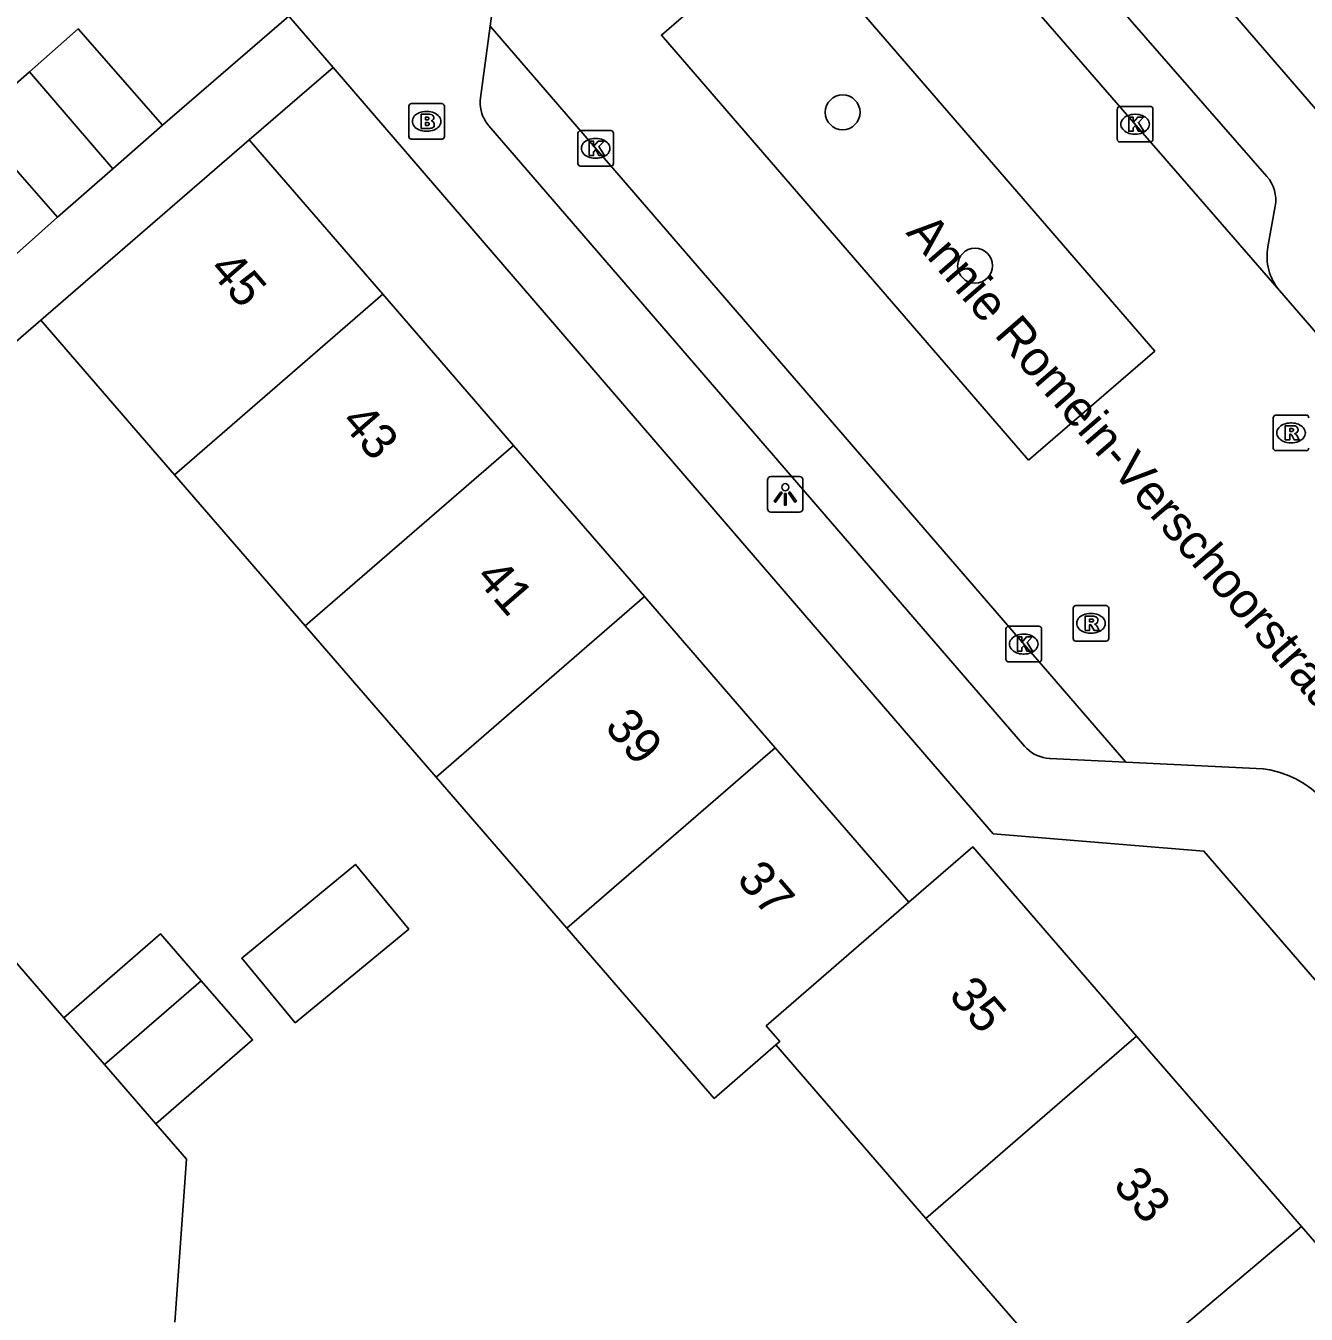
# Model space of a CAD drawing. Extents: x 160304 to 160954, y 383686 to 384161.
# Drawn here: x 160422.39 to 160458.42, y 384042.77 to 384079.01 of the extents above; entities that cross this region are included whole.
import ezdxf

# ---------------------------------------------------------------- set-up
doc = ezdxf.new("R2010")
doc.units = 0
for name, color, linetype in [('IMGEO_Boom', 7, 'Continuous'), ('IMGEO_Brandkraan', 7, 'Continuous'), ('IMGEO_Kolk', 7, 'Continuous'), ('IMGEO_Lichtpunt', 7, 'Continuous'), ('IMGEO_Openbare_ruimte_label', 7, 'Continuous'), ('IMGEO_Pand', 7, 'Continuous'), ('IMGEO_Pand_nummerreeks', 7, 'Continuous'), ('IMGEO_Rijbaan_lokaal_open', 7, 'Continuous'), ('IMGEO_Rioolput', 7, 'Continuous'), ('IMGEO_Voetpad_open', 7, 'Continuous')]:
    doc.layers.add(name, color=color, linetype=linetype)

msp = doc.modelspace()

# ---------------------------------------------------------------- linework, layer by layer
at = {"layer": 'IMGEO_Boom'}
for centre in [(160445.372, 384076.571), (160449.097, 384072.258)]:
    msp.add_circle(centre, 0.489, dxfattribs=at)
at = {"layer": 'IMGEO_Brandkraan'}
for p, q in [((160433.167, 384075.891), (160433.167, 384076.743)), ((160433.242, 384076.817), (160434.094, 384076.817)), ((160434.168, 384076.743), (160434.168, 384075.891)), ((160433.655, 384076.597), (160433.68, 384076.597)), ((160433.678, 384076.037), (160433.653, 384076.037)), ((160434.094, 384075.817), (160433.242, 384075.817))]:
    msp.add_line(p, q, dxfattribs=at)
for points in [[(160433.167, 384075.891), (160433.167, 384076.743)], [(160433.242, 384076.817), (160434.094, 384076.817)], [(160434.168, 384076.743), (160434.168, 384075.891)], [(160433.515, 384076.517), (160433.515, 384076.117), (160433.728, 384076.117)], [(160433.746, 384076.517), (160433.515, 384076.517)], [(160433.694, 384076.436), (160433.64, 384076.436), (160433.64, 384076.36)], [(160433.64, 384076.36), (160433.693, 384076.36)], [(160433.702, 384076.284), (160433.64, 384076.284), (160433.64, 384076.203)], [(160433.64, 384076.203), (160433.702, 384076.203)], [(160434.094, 384075.817), (160433.242, 384075.817)]]:
    msp.add_lwpolyline(points, dxfattribs=at)
for centre, radius, start, end in [((160433.244, 384076.741), 0.0765, 91.552, 178.448), ((160433.244, 384076.741), 0.0765, 91.552, 178.448), ((160434.092, 384076.741), 0.0765, 1.552, 88.448), ((160434.092, 384076.741), 0.0765, 1.552, 88.448), ((160433.695, 384076.398), 0.0379, 267.8285, 90.9355), ((160433.703, 384076.243), 0.0404, 269.8759, 90.5077), ((160433.75, 384076.372), 0.145, 59.4692, 91.5367), ((160433.775, 384076.419), 0.0922, 285.5137, 58.1501), ((160433.78, 384076.227), 0.105, 301.3115, 78.989), ((160433.244, 384075.893), 0.0765, 181.552, 268.448), ((160433.244, 384075.893), 0.0765, 181.552, 268.448), ((160433.734, 384076.368), 0.251, 268.6676, 293.5347), ((160434.092, 384075.893), 0.0765, 271.552, 358.448), ((160434.092, 384075.893), 0.0765, 271.552, 358.448)]:
    msp.add_arc(centre, radius, start, end, dxfattribs=at)
for centre, major_axis, ratio, start_param, end_param in [((160433.654, 384076.317), (-0.387, 0.002), 0.722429, 4.712389, 7.853982), ((160433.679, 384076.317), (-0.39, 0.002), 0.717154, 1.570796, 4.712389)]:
    msp.add_ellipse(centre, major_axis=major_axis, ratio=ratio, start_param=start_param, end_param=end_param, dxfattribs=at)
at = {"layer": 'IMGEO_Kolk'}
for p, q in [((160453.1, 384075.811), (160453.1, 384076.663)), ((160453.175, 384076.737), (160454.027, 384076.737)), ((160454.101, 384076.663), (160454.101, 384075.811)), ((160453.588, 384076.517), (160453.613, 384076.517)), ((160437.923, 384075.132), (160437.923, 384075.984)), ((160437.998, 384076.058), (160438.85, 384076.058)), ((160438.924, 384075.984), (160438.924, 384075.132)), ((160453.611, 384075.957), (160453.586, 384075.957)), ((160438.411, 384075.838), (160438.436, 384075.838)), ((160454.027, 384075.737), (160453.175, 384075.737)), ((160438.434, 384075.278), (160438.409, 384075.278)), ((160438.85, 384075.058), (160437.998, 384075.058)), ((160450.042, 384062.114), (160450.894, 384062.114)), ((160449.967, 384061.188), (160449.967, 384062.04)), ((160450.455, 384061.894), (160450.48, 384061.894)), ((160450.968, 384062.04), (160450.968, 384061.188)), ((160450.894, 384061.114), (160450.042, 384061.114)), ((160450.478, 384061.334), (160450.453, 384061.334))]:
    msp.add_line(p, q, dxfattribs=at)
for points in [[(160453.1, 384075.811), (160453.1, 384076.663)], [(160453.175, 384076.737), (160454.027, 384076.737)], [(160454.101, 384076.663), (160454.101, 384075.811)], [(160453.421, 384076.437), (160453.544, 384076.437), (160453.544, 384076.286), (160453.674, 384076.437), (160453.838, 384076.437), (160453.692, 384076.286), (160453.845, 384076.037), (160453.693, 384076.037), (160453.608, 384076.201), (160453.544, 384076.134), (160453.544, 384076.037), (160453.421, 384076.037), (160453.421, 384076.437)], [(160437.923, 384075.132), (160437.923, 384075.984)], [(160437.998, 384076.058), (160438.85, 384076.058)], [(160438.924, 384075.984), (160438.924, 384075.132)], [(160438.244, 384075.758), (160438.367, 384075.758), (160438.367, 384075.607), (160438.497, 384075.758), (160438.661, 384075.758), (160438.515, 384075.607), (160438.668, 384075.358), (160438.516, 384075.358), (160438.431, 384075.522), (160438.367, 384075.455), (160438.367, 384075.358), (160438.244, 384075.358), (160438.244, 384075.758)], [(160454.027, 384075.737), (160453.175, 384075.737)], [(160438.85, 384075.058), (160437.998, 384075.058)], [(160450.042, 384062.114), (160450.894, 384062.114)], [(160449.967, 384061.188), (160449.967, 384062.04)], [(160450.288, 384061.814), (160450.411, 384061.814), (160450.411, 384061.663), (160450.541, 384061.814), (160450.705, 384061.814), (160450.559, 384061.663), (160450.712, 384061.414), (160450.56, 384061.414), (160450.475, 384061.578), (160450.411, 384061.511), (160450.411, 384061.414), (160450.288, 384061.414), (160450.288, 384061.814)], [(160450.968, 384062.04), (160450.968, 384061.188)], [(160450.894, 384061.114), (160450.042, 384061.114)]]:
    msp.add_lwpolyline(points, dxfattribs=at)
for centre, start, end in [((160453.177, 384076.661), 91.552, 178.448), ((160453.177, 384076.661), 91.552, 178.448), ((160454.025, 384076.661), 1.552, 88.448), ((160454.025, 384076.661), 1.552, 88.448), ((160438, 384075.982), 91.552, 178.448), ((160438, 384075.982), 91.552, 178.448), ((160438.848, 384075.982), 1.552, 88.448), ((160438.848, 384075.982), 1.552, 88.448), ((160453.177, 384075.813), 181.552, 268.448), ((160453.177, 384075.813), 181.552, 268.448), ((160454.025, 384075.813), 271.552, 358.448), ((160454.025, 384075.813), 271.552, 358.448), ((160438, 384075.134), 181.552, 268.448), ((160438, 384075.134), 181.552, 268.448), ((160438.848, 384075.134), 271.552, 358.448), ((160438.848, 384075.134), 271.552, 358.448), ((160450.044, 384062.038), 91.552, 178.448), ((160450.044, 384062.038), 91.552, 178.448), ((160450.892, 384062.038), 1.552, 88.448), ((160450.892, 384062.038), 1.552, 88.448), ((160450.044, 384061.19), 181.552, 268.448), ((160450.044, 384061.19), 181.552, 268.448), ((160450.892, 384061.19), 271.552, 358.448), ((160450.892, 384061.19), 271.552, 358.448)]:
    msp.add_arc(centre, 0.0765, start, end, dxfattribs=at)
for centre, major_axis, ratio, start_param, end_param in [((160453.587, 384076.237), (-0.387, 0.002), 0.722429, 4.712389, 7.853982), ((160453.612, 384076.237), (-0.39, 0.002), 0.717154, 1.570796, 4.712389), ((160438.41, 384075.558), (-0.387, 0.002), 0.722429, 4.712389, 7.853982), ((160438.435, 384075.558), (-0.39, 0.002), 0.717154, 1.570796, 4.712389), ((160450.454, 384061.614), (-0.387, 0.002), 0.722429, 4.712389, 7.853982), ((160450.479, 384061.614), (-0.39, 0.002), 0.717154, 1.570796, 4.712389)]:
    msp.add_ellipse(centre, major_axis=major_axis, ratio=ratio, start_param=start_param, end_param=end_param, dxfattribs=at)
at = {"layer": 'IMGEO_Lichtpunt'}
for p, q in [((160443.259, 384066.23), (160443.259, 384065.423)), ((160443.259, 384066.23), (160443.259, 384065.423)), ((160444.161, 384066.325), (160443.353, 384066.325)), ((160444.161, 384066.325), (160443.353, 384066.325)), ((160444.255, 384065.423), (160444.255, 384066.23)), ((160444.255, 384065.423), (160444.255, 384066.23)), ((160443.353, 384065.329), (160444.161, 384065.329)), ((160443.353, 384065.329), (160444.161, 384065.329))]:
    msp.add_line(p, q, dxfattribs=at)
for points in [[(160443.633, 384065.894), (160443.672, 384065.866), (160443.484, 384065.604), (160443.446, 384065.631), (160443.633, 384065.894)], [(160443.735, 384065.846), (160443.782, 384065.846), (160443.782, 384065.524), (160443.735, 384065.524), (160443.735, 384065.846)], [(160443.845, 384065.866), (160443.883, 384065.893), (160444.07, 384065.631), (160444.031, 384065.603), (160443.845, 384065.866)]]:
    msp.add_lwpolyline(points, dxfattribs=at)
msp.add_circle((160443.758, 384066.028), 0.0994, dxfattribs=at)
for centre, start, end in [((160443.353, 384066.23), 90, 180), ((160443.353, 384066.23), 90, 180), ((160444.161, 384066.23), 0, 90), ((160444.161, 384066.23), 0, 90), ((160443.353, 384065.423), 180, 270), ((160443.353, 384065.423), 180, 270), ((160444.161, 384065.423), 270, 0), ((160444.161, 384065.423), 270, 360)]:
    msp.add_arc(centre, 0.0946, start, end, dxfattribs=at)
at = {"layer": 'IMGEO_Pand'}
for points in [[(160422.49, 384077.712), (160423.865, 384078.917), (160426.238, 384076.21)], [(160423.281, 384073.618), (160420.909, 384076.326), (160422.49, 384077.712)], [(160422.49, 384077.712), (160424.84, 384074.985)], [(160426.238, 384076.21), (160424.84, 384074.985)], [(160422.81, 384070.722), (160428.673, 384075.798)], [(160428.673, 384075.798), (160432.433, 384071.455)], [(160424.84, 384074.985), (160423.281, 384073.618)], [(160432.433, 384071.455), (160426.571, 384066.379)], [(160432.433, 384071.455), (160436.115, 384067.202)], [(160426.571, 384066.379), (160426.083, 384066.942), (160422.81, 384070.722)], [(160430.253, 384062.126), (160436.115, 384067.202)], [(160436.115, 384067.202), (160439.796, 384062.95)], [(160430.253, 384062.126), (160426.571, 384066.379)], [(160433.934, 384057.873), (160439.796, 384062.95)], [(160439.796, 384062.95), (160443.478, 384058.697)], [(160433.934, 384057.873), (160430.253, 384062.126)], [(160443.478, 384058.697), (160437.615, 384053.621)], [(160443.478, 384058.697), (160447.238, 384054.354)], [(160437.615, 384053.621), (160433.934, 384057.873)], [(160447.238, 384054.354), (160449.036, 384055.91), (160453.642, 384050.589)], [(160429.965, 384050.959), (160428.465, 384052.779), (160431.665, 384055.417), (160433.165, 384053.597), (160429.965, 384050.959)], [(160447.238, 384054.354), (160443.223, 384050.875), (160443.602, 384050.436), (160443.491, 384050.34)], [(160423.46, 384051.105), (160426.181, 384053.464), (160427.323, 384052.147)], [(160443.491, 384050.34), (160441.756, 384048.838), (160437.615, 384053.621)], [(160424.601, 384049.789), (160427.323, 384052.147)], [(160427.323, 384052.147), (160428.769, 384050.479), (160426.048, 384048.12)], [(160424.601, 384049.789), (160423.46, 384051.105)], [(160447.717, 384045.459), (160453.642, 384050.589)], [(160453.642, 384050.589), (160458.283, 384045.229)], [(160447.717, 384045.459), (160443.491, 384050.34)], [(160426.048, 384048.12), (160424.601, 384049.789)], [(160452.287, 384040.18), (160447.717, 384045.459)], [(160452.287, 384040.18), (160458.283, 384045.229)], [(160458.283, 384045.229), (160461.083, 384041.994)]]:
    msp.add_lwpolyline(points, dxfattribs=at)
at = {"layer": 'IMGEO_Rijbaan_lokaal_open'}
for points in [[(160443.203, 384088.215), (160457.659, 384071.56)], [(160435.453, 384078.998), (160435.838, 384081.866)], [(160450.6, 384066.79), (160454.152, 384069.858), (160443.825, 384081.814), (160440.273, 384078.746), (160450.6, 384066.79)], [(160453.335, 384058.295), (160435.453, 384078.998)], [(160457.659, 384071.56), (160461.416, 384067.232)], [(160459.355, 384056.713), (160458.945, 384057.195), (160458.761, 384057.379), (160458.562, 384057.545), (160458.348, 384057.693), (160458.122, 384057.821), (160457.886, 384057.929), (160457.64, 384058.015), (160457.388, 384058.078), (160457.205, 384058.11), (160453.335, 384058.295)], [(160418.58, 384056.734), (160423.46, 384051.105)], [(160426.048, 384048.12), (160426.908, 384047.127), (160426.58, 384042.539)]]:
    msp.add_lwpolyline(points, dxfattribs=at)
at = {"layer": 'IMGEO_Rioolput'}
for p, q in [((160457.488, 384067.129), (160457.488, 384067.981)), ((160457.563, 384068.055), (160458.415, 384068.055)), ((160457.976, 384067.835), (160458.001, 384067.835)), ((160457.999, 384067.275), (160457.974, 384067.275)), ((160458.415, 384067.055), (160457.563, 384067.055)), ((160451.858, 384061.772), (160451.858, 384062.624)), ((160451.933, 384062.698), (160452.785, 384062.698)), ((160452.346, 384062.478), (160452.371, 384062.478)), ((160452.859, 384062.624), (160452.859, 384061.772)), ((160452.369, 384061.918), (160452.344, 384061.918)), ((160452.785, 384061.698), (160451.933, 384061.698))]:
    msp.add_line(p, q, dxfattribs=at)
for points in [[(160457.488, 384067.129), (160457.488, 384067.981)], [(160457.563, 384068.055), (160458.415, 384068.055)], [(160458.077, 384067.753), (160457.825, 384067.755), (160457.825, 384067.355)], [(160458.003, 384067.674), (160457.949, 384067.674), (160457.949, 384067.593)], [(160457.949, 384067.593), (160458.001, 384067.593)], [(160457.825, 384067.355), (160457.949, 384067.355), (160457.949, 384067.517), (160457.96, 384067.517)], [(160458.007, 384067.488), (160458.078, 384067.355), (160458.218, 384067.355), (160458.153, 384067.481)], [(160458.415, 384067.055), (160457.563, 384067.055)], [(160451.858, 384061.772), (160451.858, 384062.624)], [(160451.933, 384062.698), (160452.785, 384062.698)], [(160452.859, 384062.624), (160452.859, 384061.772)], [(160452.447, 384062.396), (160452.195, 384062.398), (160452.195, 384061.998)], [(160452.195, 384061.998), (160452.319, 384061.998), (160452.319, 384062.16), (160452.33, 384062.16)], [(160452.373, 384062.317), (160452.319, 384062.317), (160452.319, 384062.236)], [(160452.319, 384062.236), (160452.371, 384062.236)], [(160452.377, 384062.131), (160452.448, 384061.998), (160452.588, 384061.998), (160452.523, 384062.124)], [(160452.785, 384061.698), (160451.933, 384061.698)]]:
    msp.add_lwpolyline(points, dxfattribs=at)
for centre, radius, start, end in [((160457.565, 384067.979), 0.0765, 91.552, 178.448), ((160457.565, 384067.979), 0.0765, 91.552, 178.448), ((160458.413, 384067.979), 0.0765, 1.552, 88.448), ((160458.413, 384067.979), 0.0765, 1.552, 88.448), ((160457.985, 384067.782), 0.19, 274.7715, 282.9687), ((160458.009, 384067.578), 0.0964, 77.0061, 93.1865), ((160458.023, 384067.635), 0.0378, 276.6634, 79.6772), ((160458.076, 384067.643), 0.109, 350.3612, 89.416), ((160458.074, 384067.643), 0.112, 277.5842, 350.9817), ((160457.959, 384067.464), 0.0533, 26.0293, 88.6989), ((160458.058, 384067.428), 0.108, 29.5134, 73.7905), ((160457.565, 384067.131), 0.0765, 181.552, 268.448), ((160457.565, 384067.131), 0.0765, 181.552, 268.448), ((160458.413, 384067.131), 0.0765, 271.552, 358.448), ((160458.413, 384067.131), 0.0765, 271.552, 358.448), ((160451.935, 384062.622), 0.0765, 91.552, 178.448), ((160451.935, 384062.622), 0.0765, 91.552, 178.448), ((160452.783, 384062.622), 0.0765, 1.552, 88.448), ((160452.783, 384062.622), 0.0765, 1.552, 88.448), ((160452.329, 384062.107), 0.0533, 26.0293, 88.6989), ((160452.355, 384062.425), 0.19, 274.7715, 282.9687), ((160452.379, 384062.221), 0.0964, 77.0061, 93.1865), ((160452.393, 384062.278), 0.0378, 276.6634, 79.6772), ((160452.446, 384062.286), 0.109, 350.3612, 89.416), ((160452.444, 384062.286), 0.112, 277.5842, 350.9817), ((160452.428, 384062.071), 0.108, 29.5134, 73.7905), ((160451.935, 384061.774), 0.0765, 181.552, 268.448), ((160451.935, 384061.774), 0.0765, 181.552, 268.448), ((160452.783, 384061.774), 0.0765, 271.552, 358.448), ((160452.783, 384061.774), 0.0765, 271.552, 358.448)]:
    msp.add_arc(centre, radius, start, end, dxfattribs=at)
for centre, major_axis, ratio, start_param, end_param in [((160457.975, 384067.555), (-0.387, 0.002), 0.722429, 4.712389, 7.853982), ((160458, 384067.555), (-0.39, 0.002), 0.717154, 1.570796, 4.712389), ((160452.345, 384062.198), (-0.387, 0.002), 0.722429, 4.712389, 7.853982), ((160452.37, 384062.198), (-0.39, 0.002), 0.717154, 1.570796, 4.712389)]:
    msp.add_ellipse(centre, major_axis=major_axis, ratio=ratio, start_param=start_param, end_param=end_param, dxfattribs=at)
at = {"layer": 'IMGEO_Voetpad_open'}
for points in [[(160482.27, 384043.068), (160464.114, 384064.194), (160464.179, 384070.303), (160445.759, 384091.611)], [(160446.192, 384087.508), (160457.311, 384074.767)], [(160426.238, 384076.21), (160429.791, 384079.277)], [(160431.035, 384077.833), (160429.791, 384079.277)], [(160435.453, 384078.998), (160435.184, 384076.979), (160435.176, 384076.891), (160435.176, 384076.802), (160435.183, 384076.713), (160435.199, 384076.626), (160435.222, 384076.54), (160435.253, 384076.457), (160435.292, 384076.377), (160435.337, 384076.3), (160435.389, 384076.228), (160435.418, 384076.193), (160450.49, 384058.744), (160450.551, 384058.679), (160450.617, 384058.62), (160450.689, 384058.567), (160450.764, 384058.521), (160450.844, 384058.481), (160450.927, 384058.449), (160451.013, 384058.424), (160451.1, 384058.408), (160451.188, 384058.399), (160451.198, 384058.398), (160453.335, 384058.295)], [(160431.035, 384077.833), (160428.673, 384075.798)], [(160464.755, 384045.129), (160455.536, 384055.791), (160449.608, 384056.274), (160431.035, 384077.833)], [(160457.542, 384073.932), (160457.335, 384072.788)], [(160417.537, 384068.495), (160423.281, 384073.618)], [(160413.467, 384062.631), (160414.841, 384063.823), (160422.81, 384070.722)]]:
    msp.add_lwpolyline(points, dxfattribs=at)
for centre, radius, start, end in [((160456.552, 384074.108), 1.005, 349.9323, 40.9956), ((160458.815, 384072.522), 1.503, 169.7966, 219.764)]:
    msp.add_arc(centre, radius, start, end, dxfattribs=at)

# ---------------------------------------------------------------- texts
at = {"layer": 'IMGEO_Openbare_ruimte_label'}
msp.add_text('Annie Romein-Verschoorstraat', height=1, rotation=310.8249, dxfattribs=at).set_placement((160447.132, 384073.174))
at = {"layer": 'IMGEO_Pand_nummerreeks'}
for s, p in [('45', (160427.509, 384072.131)), ('43', (160431.222, 384067.843)), ('41', (160435.009, 384063.469)), ('39', (160438.648, 384059.265)), ('37', (160442.361, 384054.976)), ('35', (160448.327, 384051.718)), ('33', (160452.951, 384046.377))]:
    msp.add_text(s, height=1, rotation=310.8861, dxfattribs=at).set_placement(p)

doc.saveas('drawing.dxf')
